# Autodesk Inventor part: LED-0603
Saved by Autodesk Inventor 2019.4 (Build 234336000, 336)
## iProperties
Created: 2021-02
Part Number: LED-0603
Material: Generic
Document SubType Name: Modeling
Designer: Administrator
Density: 1 g/cm^3
Appearance: Default
Title: LED-0603
Author: Administrator
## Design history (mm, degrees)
feature "Body1"
body "Solid1"
